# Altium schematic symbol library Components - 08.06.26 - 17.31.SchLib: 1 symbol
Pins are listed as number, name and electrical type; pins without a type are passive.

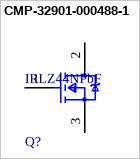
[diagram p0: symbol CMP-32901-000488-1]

## CMP-32901-000488-1
designator Q?, comment IRLZ44NPbF
MOSFET N-CH 55V 47A TO220AB; Turn-On Delay Time: 11ns; Gate to Source Voltage (Vgs): 16V; Element Configuration: Single; Rds On Max: 22mR; Turn-Off Delay Time: 26ns; Max Power Dissipation: 110W; Threshold Voltage: 2V; Drain to Source Resistance: 35mR; Input Capacitance: 1.7nF
footprint FP-PG-TO220-3-MFG
pins: 1 G, 2 D, 3 S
